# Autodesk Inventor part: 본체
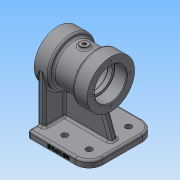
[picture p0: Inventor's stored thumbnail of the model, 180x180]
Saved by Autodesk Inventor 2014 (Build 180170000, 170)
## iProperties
Created: 2020-06
Part Number: 본체
Material: 일반
Document SubType Name: Modeling
Designer: net
Density: 1 g/cm^3
Appearance: 기본값
Mass: 268.597 g
Surface Area: 642.189 cm^2
Volume: 268.597 cm^3
Author: net
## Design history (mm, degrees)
sketch "스케치1"
  geometry: L1 (-39, 35)-(39, 35); L2 (39, 35)-(39, 0); L3 (39, 0)-(-39, 0); L4 (-39, 0)-(-39, 35); L5 (-39, 23.5)-(-21, 23.5); L6 (-21, 23.5)-(-21, 20); L7 (-21, 20)-(-15, 20); L8 (-15, 20)-(-15, 23); L9 (15, 23)-(15, 20); L10 (15, 20)-(21, 20); L11 (21, 20)-(21, 23.5); L12 (21, 23.5)-(39, 23.5); L13 (-15, 23)-(15, 23); L14 (-17, 35)-(-17, 29); L15 (-17, 29)-(17, 29); L16 (17, 29)-(17, 35); 2 further points
  constraints: 32 end point, 7 perpendicular, 4 parallel, 4 point on line, 2 equal length, 2 horizontal, 1 coincident, 1 midpoint, 1 vertical
  dimensions: "d0" = 70 diameter of L1 L3; "d1" = 78 distance between parallel lines of L4 L2; "d2" = 40 diameter of L7 L3; "d3" = 47 diameter of L12 L3; "d4" = 46 diameter of L13 L3; "d5" = 47 diameter of L5 L3; "d6" = 6 distance between parallel lines of L8 L6; "d7" = 18 distance between parallel lines of L2 L11; "d8" = 18 distance between parallel lines of L4 L6; "d9" = 30 distance between parallel lines of L9 L8; "d10" = 58 diameter of L15 L3; "d11" = 22 distance between parallel lines of L2 L16; "d12" = 22 distance between parallel lines of L4 L14
revolve "회전1" sketch "스케치1" stored, may be unused: angle "d13" = 90 deg
node "작업 평면1"
sketch "스케치2"
  geometry: 1 further point
sketch "스케치3"
  geometry: L1 (34, 49)-(-56, 49); L2 (-56, 49)-(-56, -49); L3 (-56, -49)-(34, -49); L4 (34, -49)-(34, 49); L5 (39, 35)-(39, -35) reference; 2 further points
  constraints: 8 end point, 2 parallel, 1 horizontal, 1 horizontal alignment, 1 midpoint, 1 perpendicular
  dimensions: "d15" = 98 distance of L1.end L2.end; "d16" = 90 distance of L2.end L3.end; "d17" = 5 distance between parallel lines of L5 L4
extrude "돌출1" join sketch "스케치3" distance "d18" = 10; taper "d19" = 0 deg
sketch "스케치4"
  geometry: L1 (-34, 49)-(-34, -49) reference; L2 (-34, 35)-(-24, 35); L3 (-24, 35)-(-24, 5); L4 (-24, 5)-(44, 5); L5 (44, 5)-(44, -5); L6 (44, -5)-(-24, -5); L7 (-24, -5)-(-24, -35); L8 (-24, -35)-(-34, -35); L9 (56, -49)-(56, 49) reference; L10 (-24, 5)-(-24, -5); 2 further points
  constraints: 16 end point, 4 parallel, 3 perpendicular, 2 equal length, 2 point on line, 1 collinear, 1 horizontal alignment, 1 midpoint
  dimensions: "d20" = 10 distance between parallel lines of L1 L3; "d21" = 10 distance between parallel lines of L6 L4; "d23" = 70 distance between parallel lines of L8 L2; "d38" = 12 distance between parallel lines of L9 L5
extrude "돌출2" join sketch "스케치4" stored distance "d24" = 10; taper "d25" = 0 deg
sketch "스케치5"
  geometry: L1 (56, -49)-(56, 49) reference; L2 (56, 49)-(-34, 49) reference; 5 further points
  constraints: 2 horizontal alignment, 2 vertical alignment
  dimensions: "d27" = 36 distance of point (36, 29) point (0, 29); "d28" = 58 distance of point (36, -29) point (36, 29); "d29" = 20 distance from line of L2 point (36, 29); "d30" = 20 distance from line of L1 point (36, 29)
hole "구멍1" sketch "스케치5" at (0, 29), (36, 29), (36, -29), (0, -29) diameter "d31" = 9; stored, may be unused: countersink angle "d35" = 90 deg, drill point angle "d37" = 118 deg; dims "d32" = 6, "d33" = 4, "d34" = 2, "d36" = 8
sketch "스케치6"
  geometry: L1 (44, -70)-(35.162, -45.719); L2 (44, -70)-(69.84, -70); L3 (56, -80)-(56, -70) reference; L4 (-34, -70)-(56, -70) reference; 1 further point
  constraints: 4 end point, 1 equal length, 1 horizontal, 1 point on line
  dimensions: "d39" = 110 deg angle of L2 L1; "d40" = 12 distance from line of L3 L1.start
feature "리브1" sketch "스케치6" dims "d41" = 1, "d42" = 10, "d43" = 0, "d44" = 0, "d45" = 1, "d46" = 1
fillet "모깎기1" dims "d47" = 20, "d48" = 3
sketch "스케치7"
  geometry: C1 r 35 at (0, 0) reference; 1 further point
  constraints: 1 vertical alignment
  dimensions: "d49" = 28.5 distance of C1.centre point (0, 28.5)
hole "구멍2" sketch "스케치7" at (0, 28.5) diameter "d50" = 3.242; stored, may be unused: countersink angle "d54" = 90 deg, drill point angle "d56" = 118 deg; dims "d51" = 10, "d52" = 4, "d53" = 2, "d55" = 12
node "작업 평면2"
sketch "스케치8"
  geometry: C1 r 6 at (0, 0); 1 further point
  constraints: 1 centre point, 1 coincident
  dimensions: "d61" = 12 diameter of C1
extrude "돌출3" join sketch "스케치8" stored distance "d62" = 10; taper "d63" = 0 deg
sketch "스케치9"
  geometry: C1 r 6 at (0, 0) reference
hole "구멍3" sketch "스케치9" at (0, 0) diameter "d64" = 5.188; stored, may be unused: countersink angle "d68" = 90 deg, drill point angle "d70" = 118 deg; dims "d65" = 10, "d66" = 4, "d67" = 2, "d69" = 12
node "작업 평면3"
sketch "스케치10"
  geometry: L1 (-3, 10)-(-3, 0) reference; L2 (0, 0)-(67, 0) reference; 2 further points
  constraints: 1 other
  dimensions: "d72" = 45 distance from line of L1 point (42, 4); "d73" = 4 distance from line of L2 point (42, 4)
feature "엠보싱1" sketch "스케치10" dims "d0" = 70, "d1" = 78, "d2" = 40, "d3" = 47, "d4" = 46, "d5" = 47, "d6" = 6, "d7" = 18, "d8" = 18, "d9" = 30, "d10" = 58, "d11" = 22, "d12" = 22, "d74" = 0.5, "d75" = 0
fillet "모깎기2" dims "d76" = 3
fillet "모깎기3" dims "d77" = 3
chamfer "모따기1" distance "d78" = 1; stored, may be unused: second distance "d79" = 2, angle "d80" = 45 deg
fillet "모깎기4" dims "d81" = 0.3
node "솔리드1"
pattern_circular "원형 패턴1" dims angle "d58" = 360 deg
mirror "대칭1"
other parameters: "d60" = 32, "d71" = 10.75
